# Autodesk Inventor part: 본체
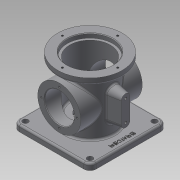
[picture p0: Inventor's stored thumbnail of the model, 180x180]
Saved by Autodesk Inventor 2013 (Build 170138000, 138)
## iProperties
Created: 2017-08
Part Number: 본체
Material: 알루미늄 6061
Document SubType Name: Modeling
Designer: mduedu
Density: 2.71 g/cm^3
Mass: 951.043 g
Surface Area: 966.502 cm^2
Volume: 350.938 cm^3
Author: mduedu
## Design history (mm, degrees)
sketch "스케치1"
  geometry: L1 (-62.5, -62.5)-(62.5, -62.5); L2 (62.5, -62.5)-(62.5, 62.5); L3 (62.5, 62.5)-(-62.5, 62.5); L4 (-62.5, 62.5)-(-62.5, -62.5); L5 (-62.5, -62.5)-(62.5, 62.5); L6 (62.5, -62.5)-(-62.5, 62.5); 1 further point
  constraints: 12 end point, 2 midpoint, 2 parallel, 1 horizontal, 1 perpendicular
  dimensions: "d232" = 125 distance of L3.end L2.end; "d233" = 125 distance of L2.end L1.end
extrude "돌출1" new body sketch "스케치1" distance "d5" = 10; taper "d6" = 0 deg
sketch "스케치2"
  geometry: C1 r 38 at (0, 0); 1 further point
  constraints: 1 centre point, 1 coincident
  dimensions: "d111" = 76 diameter of C1
extrude "돌출2" join sketch "스케치2" distance "d12" = 88; taper "d13" = 0 deg
sketch "스케치3"
  geometry: C1 r 52.5 at (0, 0); 1 further point
  constraints: 1 centre point, 1 coincident
  dimensions: "d114" = 105 diameter of C1
extrude "돌출3" join sketch "스케치3" distance "d19" = 10; taper "d20" = 0 deg
sketch "스케치4"
  geometry: C1 r 33 at (0, 0); 1 further point
  constraints: 1 centre point, 1 coincident
  dimensions: "d115" = 66 diameter of C1
extrude "돌출4" cut sketch "스케치4" distance "d26" = 86; taper "d27" = 0 deg
sketch "스케치5"
  geometry: C1 r 37 at (0, 0); 1 further point
  constraints: 1 centre point, 1 coincident
  dimensions: "d116" = 74 diameter of C1
extrude "돌출5" cut sketch "스케치5" distance "d29" = 7; taper "d30" = 0 deg
node "작업 평면1"
sketch "스케치18"
  geometry: L1 (-62.5, 0)-(62.5, 0) reference; C1 r 35 at (0, 54); 1 further point
  constraints: 1 centre point, 1 vertical alignment
  dimensions: "d118" = 70 diameter of C1; "d234" = 54 distance from line of C1.centre L1
extrude "돌출9" join sketch "스케치18" stored distance "d120" = 10; taper "d121" = 0 deg
hole "구멍8" diameter "d124" = 48; stored, may be unused: countersink angle "d128" = 90 deg, drill point angle "d130" = 118 deg; dims "d122" = 10, "d123" = 10, "d125" = 6, "d126" = 4, "d127" = 2, "d129" = 8
sketch "스케치9"
  geometry: C1 r 33 at (0, 0); 1 further point
  constraints: 1 centre point, 1 coincident
  dimensions: "d131" = 66 diameter of C1
extrude "돌출8" cut sketch "스케치9" distance "d43" = 16; taper "d44" = 0 deg
node "작업 평면2"
fillet "모깎기9" dims "d137" = 3
fillet "모깎기10" dims "d138" = 3
chamfer "모따기2" distance "d139" = 1; stored, may be unused: second distance "d140" = 2, angle "d141" = 45 deg
fillet "모깎기11" dims "d142" = 3
fillet "모깎기12" dims "d143" = 3
fillet "모깎기13" dims "d144" = 3
node "작업 평면3"
sketch "스케치20"
  geometry: L1 (108, -52.5)-(108, 52.5) reference; L2 (37, 7)-(71, 7); L3 (37, -7)-(71, -7); L4 (0, -33)-(0, 33) reference; A1 r 7 centre (37, 0) between (37, 7) and (37, -7); A2 r 7 centre (71, 0) between (71, 7) and (71, -7); 1 further point
  constraints: 4 end point, 4 point on circle, 3 tangent, 2 centre point, 2 horizontal alignment, 1 parallel, 1 perpendicular
  dimensions: "d203" = 14 diameter of A1; "d206" = 30 distance edge to line of A2 L1; "d207" = 48 dimension on A2 A1 (derived); "d236" = 30 distance edge to line of A1 L4
extrude "돌출10" join sketch "스케치20" stored distance "d152" = 10; taper "d153" = 10 deg
sketch "스케치21"
  geometry: C1 r 7 at (0, 71) reference; C2 r 7 at (0, 37) reference; 3 further points
  constraints: 2 coincident
hole "구멍12" sketch "스케치21" at (0, 71), (0, 37) diameter "d219" = 4.134; stored, may be unused: countersink angle "d223" = 90 deg, drill point angle "d225" = 118 deg; dims "d220" = 6, "d221" = 4, "d222" = 2, "d224" = 8
fillet "모깎기18" dims "d229" = 3
sketch "스케치23"
  geometry: C1 r 20 at (0, 0); 1 further point
  constraints: 1 centre point, 1 coincident
  dimensions: "d168" = 40 diameter of C1
extrude "돌출12" cut sketch "스케치23" stored distance "d169" = 148.25; taper "d170" = 0 deg
sketch "스케치28"
  geometry: L1 (62.5, -62.5)-(62.5, 62.5) reference; 2 further points
  constraints: 1 horizontal alignment, 1 other
  dimensions: "d238" = 10 distance from line of point (52.5, 0) L1
feature "엠보싱4" sketch "스케치28" dims "d239" = 0.5, "d240" = 0
sketch "스케치25" dims "d178" = 58
  geometry: C1 r 35 at (0, 0) reference; 3 further points
  constraints: 2 vertical alignment, 1 coincident, 2 other
hole "구멍10" sketch "스케치25" at (0, 29) diameter "d179" = 3.242; stored, may be unused: countersink angle "d183" = 90 deg, drill point angle "d185" = 118 deg; dims "d180" = 4, "d181" = 4, "d182" = 2, "d184" = 6
sketch "스케치26" dims "d189" = 90
  geometry: 3 further points
  constraints: 2 vertical alignment, 1 coincident, 2 other
hole "구멍11" sketch "스케치26" at (0, 45) diameter "d190" = 3.242; stored, may be unused: countersink angle "d194" = 90 deg, drill point angle "d196" = 118 deg; dims "d191" = 4, "d192" = 4, "d193" = 2, "d195" = 6
chamfer "모따기4" distance "d200" = 1; stored, may be unused: second distance "d201" = 2, angle "d202" = 45 deg
fillet "모깎기19" dims "d241" = 10
sketch "스케치29"
  geometry: A1 r 10 centre (-52.5, 52.5) between (-52.5, 62.5) and (-62.5, 52.5) reference; A2 r 10 centre (52.5, 52.5) between (62.5, 52.5) and (52.5, 62.5) reference; A3 r 10 centre (52.5, -52.5) between (52.5, -62.5) and (62.5, -52.5) reference; A4 r 10 centre (-52.5, -52.5) between (-62.5, -52.5) and (-52.5, -62.5) reference; 5 further points
  constraints: 4 coincident
hole "구멍13" sketch "스케치29" at (-52.5, 52.5), (52.5, 52.5), (52.5, -52.5), (-52.5, -52.5) diameter "d242" = 9; stored, may be unused: countersink angle "d246" = 90 deg, drill point angle "d248" = 118 deg; dims "d243" = 6, "d244" = 4, "d245" = 2, "d247" = 8
fillet "모깎기20" dims "d249" = 3
node "솔리드1"
mirror "대칭2"
pattern_circular "원형 패턴1" dims angle "d187" = 360 deg
mirror "대칭3"
pattern_circular "원형 패턴2" dims angle "d198" = 360 deg
other parameters: "d147" = 58
